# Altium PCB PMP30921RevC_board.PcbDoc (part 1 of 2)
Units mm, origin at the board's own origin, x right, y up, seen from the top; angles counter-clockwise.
Board outline 80.01 x 39.37 mm, 2 copper layers (Top Layer, Bottom Layer), stack 1.575 mm thick; 86 components, 35 nets, 198 pads, 30 vias.
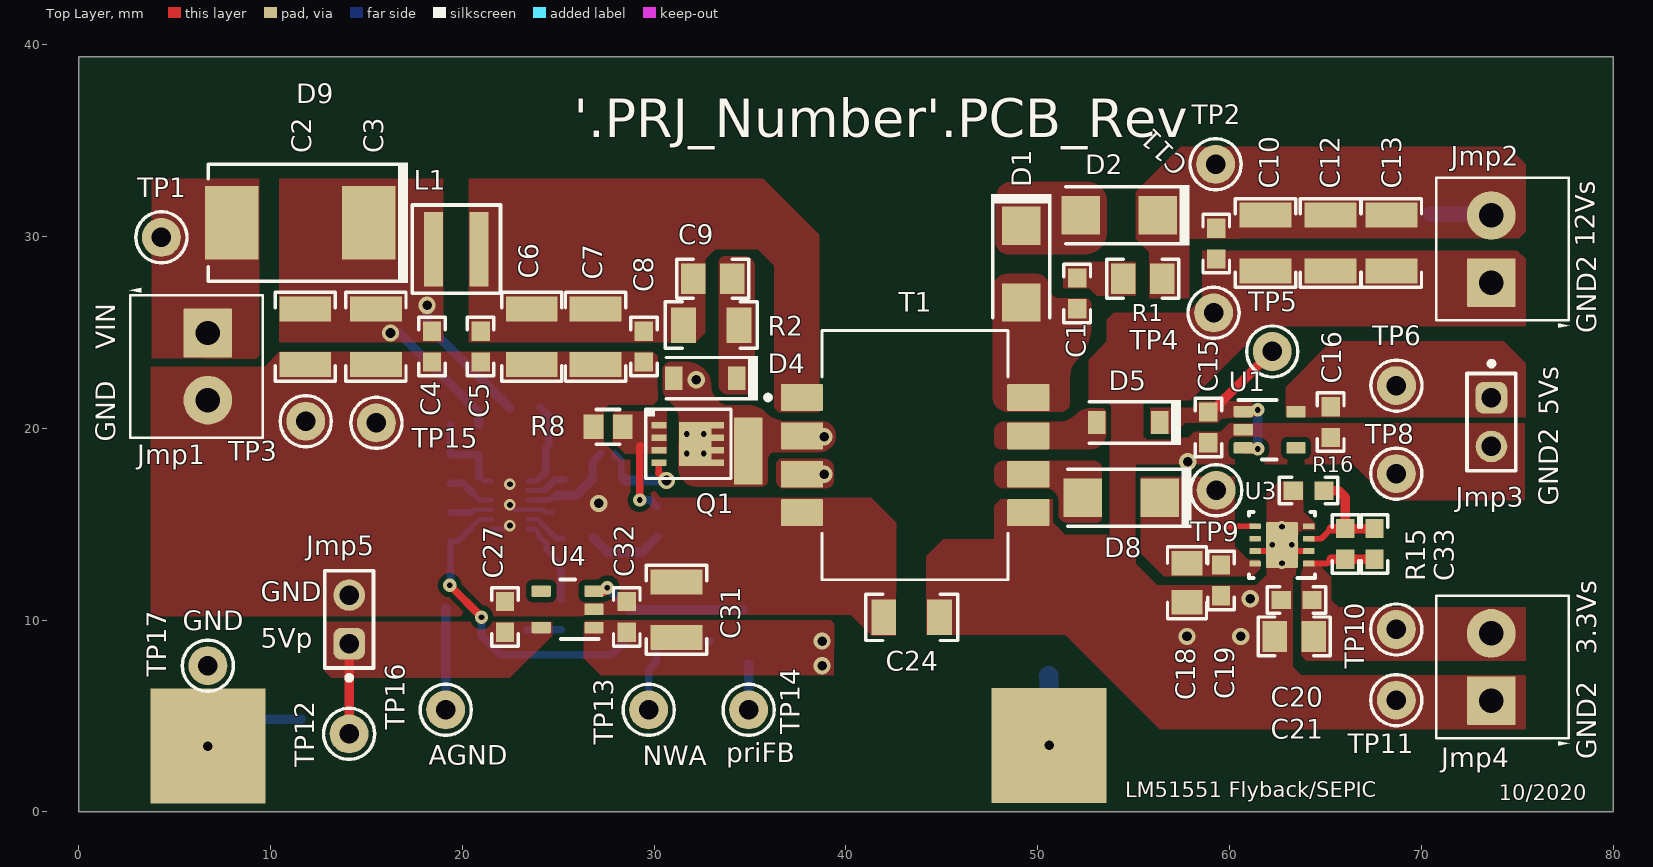
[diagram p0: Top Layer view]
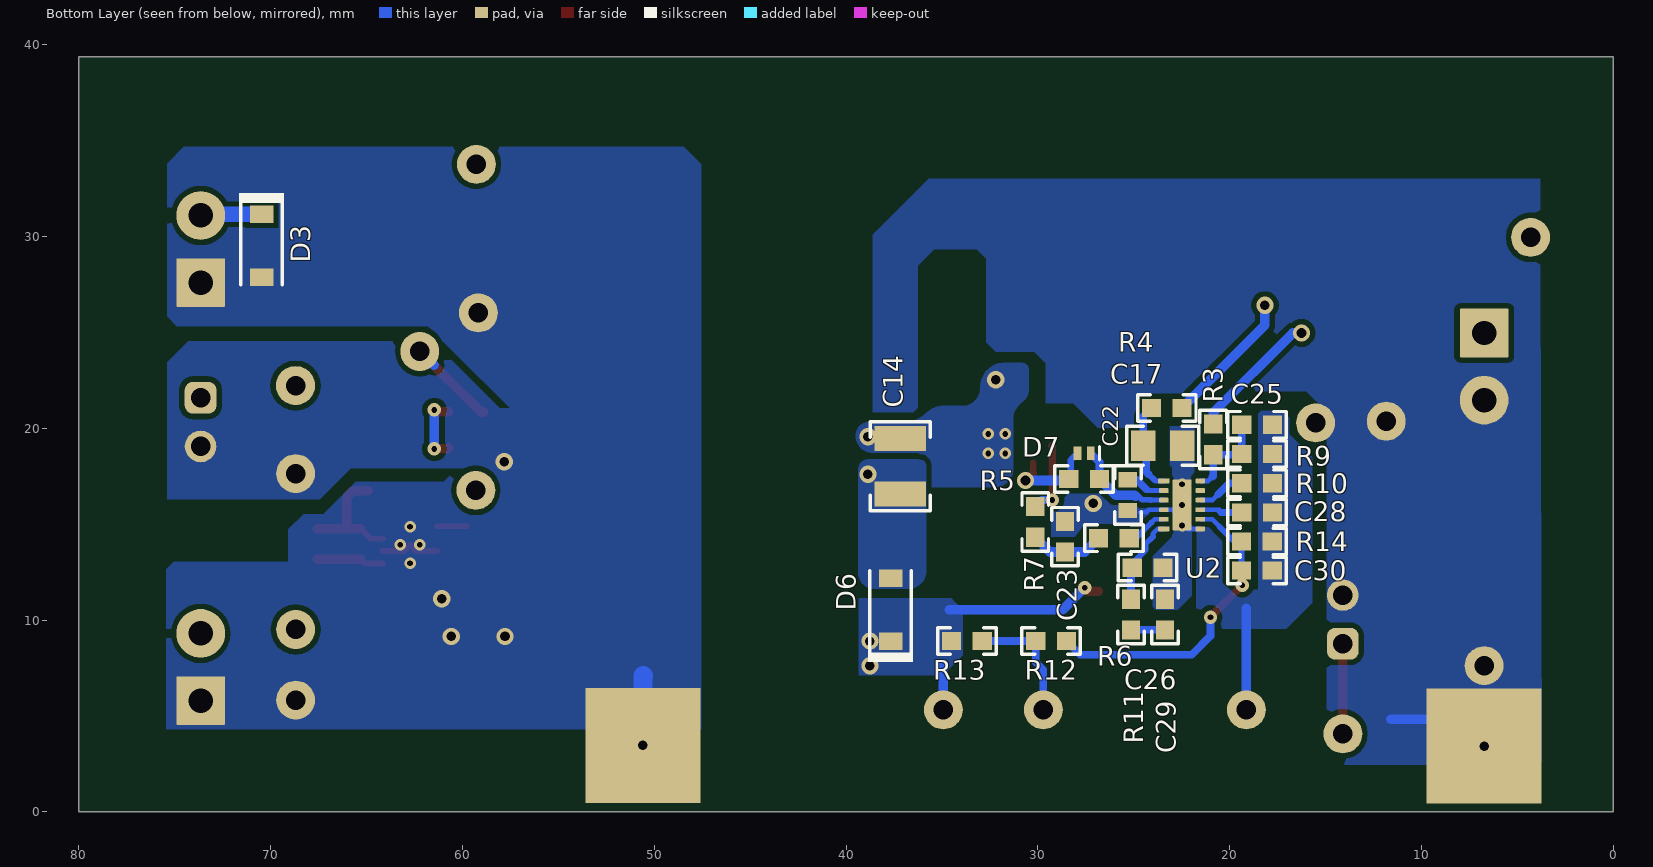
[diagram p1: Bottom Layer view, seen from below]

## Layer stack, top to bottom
Top Solder: solder mask 0.0102, Solder Resist, Dk 3.5
Top Layer: signal copper 0.0356
Dielectric1: core 1.5037, FR-4, Dk 4.8
Bottom Layer: signal copper 0.0356
Bottom Solder: solder mask 0.0102, Solder Resist, Dk 3.5

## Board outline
0,0 80.01,0 80.01,39.37 0,39.37

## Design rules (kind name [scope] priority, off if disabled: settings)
AcuteAngle [All] p1: minimum=4.50000000000000E+0001 checktracksonly=FALSE
AssemblyTestPointUsage [All] p1: valid=2
BoardOutlineClearance BoardOutlineClearance_MountingHoles [OnCopper and InComponentClass('Mounting Holes')] p1: gap=1 ignorepadtopadclearanceinfootprint=FALSE
BoardOutlineClearance BoardOutlineClearance_Poly [OnCopper and IsPoly] p2: gap=0.635 ignorepadtopadclearanceinfootprint=FALSE
BoardOutlineClearance [OnCopper and Not InComponentClass('Logo') and not InComponentClass('FiducialMark') and not InRegion(1000,500,4000,800) and not InPoly] p3: gap=1.905 ignorepadtopadclearanceinfootprint=FALSE
Clearance Clearance_Keepouts [((IsTrack Or IsArc) And Not InPoly) And IsFree and IsKeepOut vs ((IsTrack Or IsArc) And Not InPoly) And IsFree and IsKeepOut] p1: gap=0 ignorepadtopadclearanceinfootprint=FALSE
Clearance Clearance_Poly [InPolygon] p2: gap=0.28 ignorepadtopadclearanceinfootprint=TRUE
Clearance Clearance_FiducialMark [IsKeepOut and InComponentClass('FiducialMark') vs IsPad and InComponentClass('FiducialMark')] p3: gap=0 ignorepadtopadclearanceinfootprint=FALSE
Clearance [All] p4: gap=0.2 ignorepadtopadclearanceinfootprint=TRUE
ComponentClearance ComponentClearance_1 [All vs InComponent('TP7')] p1: gap=0.5 collisioncheckmode=3 verticalgap=0.254 showdistances=FALSE
ComponentClearance ComponentClearance_MountingHoles_FiducialMarks [InComponentClass('Mounting Holes') vs InComponentClass('FiducialMark')] p2: gap=1.27 collisioncheckmode=3 verticalgap=0.254 showdistances=FALSE
ComponentClearance ComponentClearance_Shunt [InComponentClass('Header') vs InComponentClass('Shunt')] p3: gap=0 collisioncheckmode=3 verticalgap=0 showdistances=FALSE
ComponentClearance ComponentClearance_Logo [InComponentClass('Logo')] p4: gap=1.27 collisioncheckmode=3 verticalgap=0.254 showdistances=FALSE
ComponentClearance ComponentClearance_ScrewToNut [(HasFootprint('NY PMS 440 0025 PH')) vs (HasFootprint('Keystone_1902C'))] p5: gap=0.127 collisioncheckmode=3 verticalgap=0.254 showdistances=FALSE
ComponentClearance ComponentClearance_MountingHoles [InComponentClass('Mounting Holes')] p6: gap=6.35 collisioncheckmode=3 verticalgap=2540 showdistances=FALSE
ComponentClearance ComponentClearance_SmallPassives [HasFootprint('0201*') or HasFootprint('0402*') or HasFootprint('0508') or HasFootprint('0603*') or HasFootprint('0612') or HasFootprint('0805*') or HasFootprint('0815*') or HasFootprint('0830*') or HasFootprint('1206*') or HasFootprint('1210*') or HasFootprint('1808*') or HasFootprint('1812*') or HasFootprint('1825*') or HasFootprint('2010*') or HasFootprint('2220*') or HasFootprint('2225*') or HasFootprint('2512*') or HasFootprint('2728*') or HasFootprint('3518*') or HasFootprint('X1-DFN1006-2') vs HasFootprint('0201*') or HasFootprint('0402*') or HasFootprint('0508') or HasFootprint('0603*') or HasFootprint('0612') or HasFootprint('0805*') or HasFootprint('0815*') or HasFootprint('0830*') or HasFootprint('1206*') or HasFootprint('1210*') or HasFootprint('1808*') or HasFootprint('1812*') or HasFootprint('1825*') or HasFootprint('2010*') or HasFootprint('2220*') or HasFootprint('2225*') or HasFootprint('2512*') or HasFootprint('2728*') or HasFootprint('3518*') or HasFootprint('X1-DFN1006-2')] p7: gap=0.38 collisioncheckmode=3 verticalgap=0.254 showdistances=FALSE
ComponentClearance ComponentClearance_THtoSMT [IsThruComponent vs IsSMTComponent] p8: gap=1.016 collisioncheckmode=3 verticalgap=0.762 showdistances=FALSE
ComponentClearance ComponentClearance_THtoTH [IsThruComponent vs IsThruComponent] p9: gap=0.762 collisioncheckmode=3 verticalgap=0.762 showdistances=FALSE
ComponentClearance [All] p10: gap=0.762 collisioncheckmode=3 verticalgap=0.254 showdistances=FALSE
DiffPairsRouting [All] p1: maxlimit=2.54 minlimit=0.254 mostfreqgap=0.254 toplayer_minwidth=0.381 toplayer_maxwidth=0.381 toplayer_prefwidth=0.381 bottomlayer_minwidth=0.381 bottomlayer_maxwidth=0.381 bottomlayer_prefwidth=0.381 maxuncoupledlength=25.4
FabricationTestPointUsage TestPointUsage [All] p1: valid=2 allowmultiple=FALSE
FabricationTestpoint Testpoint [All] p1: side=3 testpointundercomponent=TRUE minsize=1.016 maxsize=2.54 preferedsize=1.524 minholesize=0 maxholesize=1.016 preferedholesize=0.813 testpointgrid=0.025 allowsidetop=TRUE allowsidebottom=TRUE usegrid=TRUE gridtolerance=0
FanoutControl Fanout_LCC [IsLCC] p1: bgadir=Out bgaviamode=Centered fanoutstyle=Auto fanoutdirection=Alternating viagrid=0.025 // Fanout_LCC (Default Rule)
FanoutControl Fanout_BGA [IsBGA] p2: bgadir=Out bgaviamode=Centered fanoutstyle=Auto fanoutdirection=Alternating viagrid=0.025 // Fanout_BGA (Default Rule)
FanoutControl Fanout_Default [All] p4: bgadir=Out bgaviamode=Centered fanoutstyle=Auto fanoutdirection=Alternating viagrid=0.025 // Fanout_Default (Default Rule)
FanoutControl Fanout_Small [(CompPinCount < 5)] p5: bgadir=Out bgaviamode=Centered fanoutstyle=Auto fanoutdirection=OutThenIn viagrid=0.025 // Fanout_Small (Default Rule)
HoleSize [All] p1: absolutevalues=TRUE maxlimit=6.375 minlimit=0.3 maxpercent=80.000 minpercent=20.000
MinimumAnnularRing MinimumAnnularRing_ThermalPadVias [IsVia and InAnyComponent] p1: minimumring=0.15
MinimumAnnularRing [All] p2: minimumring=0.2
MinimumSolderMaskSliver MinimumSolderMaskSliver_Logo [InComponentClass('Logo') vs InComponentClass('Logo')] p1: minsoldermaskwidth=0.018
MinimumSolderMaskSliver [All] p2: minsoldermaskwidth=0.1
PlaneConnect [All] p1: planeconnectstyle=Relief reliefexpansion=0.254 reliefentries=4 reliefconductorwidth=0.254 reliefairgap=0.254
PolygonConnect [All] p1: connectstyle=Direct reliefconductorwidth=0.254 reliefentries=4 polygonreliefangle="90 Angle" airgapwidth=0.254
RoutingVias ThermalPadVias [IsVia and InAnyComponent] p1: holewidth=0.2 width=0.5 viastyle="Through Hole" minholewidth=0.2 minwidth=0.5 maxholewidth=0.33 maxwidth=0.6
RoutingVias [All] p2: holewidth=0.5 width=0.9 viastyle="Through Hole" minholewidth=0.3 minwidth=0.6 maxholewidth=1.016 maxwidth=1.651
SilkToBoardRegionClearance [Not ((IsComment or IsDesignator) And (Hide <> 'False')) and not InRegion(1000,500,4000,800)] p1:
SilkToSilkClearance SilkToSilkClearance_Pb-FreeLogo [(HasFootprint('Pb-Free_Overlay_Medium') OR HasFootprint('Pb-Free_Overlay_Small')) vs (HasFootprint('Pb-Free_Overlay_Medium') OR HasFootprint('Pb-Free_Overlay_Small'))] p1: silktosilkclearance=0
SilkToSilkClearance [All] p2: silktosilkclearance=0.1
SilkToSolderMaskClearance SilkToComponentPadClearance [(IsPad or IsFill or IsRegion) and InAnycomponent] p1: minsilkscreentomaskgap=0.127 clearancetoexposedcopper=TRUE
SilkToSolderMaskClearance "Silk to Solder Mask Opening" [All] p2: minsilkscreentomaskgap=0.1 clearancetoexposedcopper=FALSE
SolderMaskExpansion [All] p1: expansion=0.05 istentingtop=FALSE
UnRoutedNet [All] p1: checkbadconnections=TRUE
Width [All] p1: maxlimit=2.54 minlimit=0.152 preferedwidth=0.254 checkconnectedcopper=TRUE
14 further rules are at their usual default settings.

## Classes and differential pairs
component class Header: Jmp3 Jmp5
net class C33_Nets: FB NetC20_1
net class U4_Nets: GND NetC27_1 NetC31_1 NetU4_4
net class U3_Nets: FB GNDsec NetC18_1 NetC20_1 NetU3_6
net class U2_Nets: GND NetC17_1 NetC22_1 NetC25_1 NetC26_1 NetC28_1 NetC30_1 NetD7_1 NetR6_1 NetR10_2 NetU2_11
net class U1_Nets: GNDsec NetC15_1 NetC16_1 NetU1_4
net class TP17_Nets: GND
net class TP16_Nets: GND
net class TP15_Nets: GND
net class TP14_Nets: NetC31_1
net class TP13_Nets: NetR12_1
net class TP12_Nets: NetC27_1
net class TP11_Nets: GNDsec
net class TP10_Nets: NetC20_1
net class TP9_Nets: NetC18_1
net class TP8_Nets: GNDsec
net class TP6_Nets: NetC16_1
net class TP5_Nets: NetC15_1
net class TP4_Nets: GNDsec
net class TP3_Nets: GND
net class TP2_Nets: NetC10_1
net class TP1_Nets: NetD9_2
net class T1_Nets: GND GNDsec NetC1_2 NetC5_1 NetC14_1 NetC14_2 NetD5_2 NetD8_2
net class R16_Nets: FB GNDsec
net class R15_Nets: FB NetC20_1
net class R14_Nets: GND NetC30_1
net class R13_Nets: NetC31_1 NetR12_1
net class R12_Nets: NetC30_1 NetR12_1
net class R11_Nets: NetC26_1 NetC29_1
net class R10_Nets: GND NetR10_2
net class R9_Nets: GND NetC25_1
net class R8_Nets: GND NetQ1_1
net class R7_Nets: NetC23_1 NetQ1_1
net class R6_Nets: NetC23_1 NetR6_1
net class R5_Nets: NetD7_1 NetD7_2
net class R4_Nets: NetC2_1 NetC17_1
net class R3_Nets: NetC2_1 NetC25_1
net class R2_Nets: NetC5_1 NetC9_2
net class R1_Nets: NetC1_1 NetC10_1
net class Q1_Nets: NetC14_1 NetD7_2 NetQ1_1
net class L1_Nets: NetC2_1 NetC5_1
net class Jmp5_Nets: GND NetC27_1
net class Jmp4_Nets: GNDsec NetC20_1
net class Jmp3_Nets: GNDsec NetC16_1
net class Jmp2_Nets: GNDsec NetC10_1
net class Jmp1_Nets: GND NetD9_2
net class D9_Nets: NetC2_1 NetD9_2
net class D8_Nets: NetC18_1 NetD8_2
net class D7_Nets: NetD7_1 NetD7_2
net class D6_Nets: NetC14_2 NetC31_1
net class D5_Nets: NetC15_1 NetD5_2
net class D4_Nets: NetC9_2 NetC14_1
net class D3_Nets: GNDsec NetC10_1
net class D2_Nets: NetC10_1 NetD1_1
net class D1_Nets: NetC1_2 NetD1_1
net class C32_Nets: GND NetC31_1
net class C31_Nets: GND NetC31_1
net class C30_Nets: GND NetC30_1
net class C29_Nets: GND NetC29_1
net class C28_Nets: GND NetC28_1
net class C27_Nets: GND NetC27_1
net class C26_Nets: GND NetC26_1
net class C25_Nets: GND NetC25_1
net class C24_Nets: GND GNDsec
net class C23_Nets: GND NetC23_1
net class C22_Nets: GND NetC22_1
net class C21_Nets: GNDsec NetC20_1
net class C20_Nets: GNDsec NetC20_1
net class C19_Nets: GNDsec NetC18_1
net class C18_Nets: GNDsec NetC18_1
net class C17_Nets: GND NetC17_1
net class C16_Nets: GNDsec NetC16_1
net class C15_Nets: GNDsec NetC15_1
net class C14_Nets: NetC14_1 NetC14_2
net class C13_Nets: GNDsec NetC10_1
net class C12_Nets: GNDsec NetC10_1
net class C11_Nets: GNDsec NetC10_1
net class C10_Nets: GNDsec NetC10_1
net class C9_Nets: NetC5_1 NetC9_2
net class C8_Nets: GND NetC5_1
net class C7_Nets: GND NetC5_1
net class C6_Nets: GND NetC5_1
net class C5_Nets: GND NetC5_1
net class C4_Nets: GND NetC2_1
net class C3_Nets: GND NetC2_1
net class C2_Nets: GND NetC2_1
net class C1_Nets: NetC1_1 NetC1_2

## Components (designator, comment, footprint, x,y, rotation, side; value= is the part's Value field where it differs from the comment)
C1 "GRM1885C2A101JA01D" 0603#1 52.06,27.033 r270 top value=100pF
C2 "GRM32ER71H106KA12L" 1210_270 11.811,24.765 r270 top value=10uF
C3 "GRM32ER71H106KA12L" 1210_270 15.494,24.765 r270 top value=10uF
C4 "GCM188R71H104KA57D" 0603#1 18.415,24.257 r270 top value=0.1uF
C5 "GCM188R71H104KA57D" 0603#1 20.955,24.257 r270 top value=0.1uF
C6 "GRM32ER71H106KA12L" 1210_270 23.622,24.765 r270 top value=10uF
C7 "GRM32ER71H106KA12L" 1210_270 26.949,24.768 r270 top value=10uF
C8 "GCM188R71H104KA57D" 0603#1 29.464,24.257 r270 top value=0.1uF
C9 "GRM21BR72A103MA01L" 0805_HV 33.051,27.795 r0 top value=0.01uF
C10 "GRM32ER71E226KE15L" 1210_270 61.877,29.658 r270 top value=22uF
C11 "GCM188R71H104KA57D" 0603#1 59.309,29.629 r270 top value=0.1uF
C12 "GRM32ER71E226KE15L" 1210_270 65.268,29.658 r270 top value=22uF
C13 "GRM32ER71E226KE15L" 1210_270 68.443,29.658 r270 top value=22uF
C14 "GRM32ER71H106KA12L" 1210_270 37.178,18.016 r270 bottom value=10uF
C15 "GRM188Z71A106MA73D" 0603#1 58.896,20.046 r270 top value=10uF
C16 "GRM188Z71A106MA73D" 0603#1 65.278,20.32 r270 top value=10uF
C17 "GRM21BR71H105KA12L" 0805_HV 23.495,19.094 r180 bottom value=1uF
C18 "GRM21BZ71A226ME15L" 0805_HV 57.785,11.938 r270 top value=22uF
C19 "GRM188R71C104KA01D" 0603#1 59.563,12.065 r270 top value=0.1uF
C20 "GRM188R71C104KA01D" 0603#1 63.5,11.049 r180 top value=0.1uF
C21 "GRM21BZ71A226ME15L" 0805_HV 63.373,9.144 r180 top value=22uF
C22 "GRM188R71C105KA12D" 0603#2 25.312,16.514 r270 bottom value=1uF
C23 "GRM188R71E102KA01D" 0603#1 28.584,14.346 r90 bottom value=1000pF
C24 "GRM31BR73A102KW01L" 1206 43.424,10.142 r180 top value=1000pF
C25 "GRM1885C1H100JA01D" 0603#1 18.571,20.179 r180 bottom value=10pF
C26 "GRM188R71H331KA01D" 0603#1 24.279,12.731 r180 bottom value=330pF
C27 "GRM188Z71A106MA73D" 0603#1 22.225,10.16 r90 top value=10uF
C28 "GRM188R71C104KA01D" 0603#1 18.571,15.607 r180 bottom value=0.1uF
C29 "GRM188R71E104KA01D" 0603#1 23.368,10.287 r90 bottom value=0.1uF
C30 "GRM188R71H331KA01D" 0603#1 18.581,12.577 r180 bottom value=330pF
C31 "GRM32ER71A476KE15L" 1210_270 31.168,10.542 r90 top value=47uF
C32 "GRM188Z71A106MA73D" 0603#1 28.575,10.16 r90 top value=10uF
C33 "GRM188R71E103KA01D" 0603#1 67.564,13.97 r90 top value=0.01uF (schematic designator C?)
D1 "B1100-13-F" SMA 49.139,28.557 r270 top value=100V
D2 "B1100-13-F" SMA 54.251,31.097 r180 top value=100V
D3 "MMSZ5245B-7-F" SOD-123 70.475,29.522 r270 bottom value=15V
D4 "MBR0580-TP" SOD-123 32.67,22.609 r180 top value=80V
D5 "MBR0580-TP" SOD-123 54.727,20.302 r180 top value=80V
D6 "MBR0580-TP" SOD-123 37.678,10.542 r90 bottom value=80V
D7 "BAT54LP-7" X1-DFN1006-2 27.588,18.689 r0 bottom value=30V
D8 "B160-13-F" SMA 54.356,16.383 r180 top value=60V
D9 "B360-13-F" SMC 11.547,30.716 r180 top value=60V
Jmp1 "ED555/2DS" TERM_BLK_ED555-2DS 6.731,24.968 r270 top
Jmp2 "ED555/2DS" TERM_BLK_ED555-2DS 73.65,27.592 r90 top
Jmp3 "TSW-102-07-G-S" TSW-102-07-G-S 73.66,20.32 r270 top
Jmp4 "ED555/2DS" TERM_BLK_ED555-2DS 73.65,5.799 r90 top
Jmp5 "TSW-102-07-G-S" TSW-102-07-G-S 14.097,10.033 r90 top
L1 "XEL4030-222MEB" XEL4030_310 19.685,29.337 r0 top value=2.2uH
Q1 "BSZ440N10NS3 G" PG-TSDSON-8 31.789,19.181 r0 top value=100V
R1 "CRCW0805100RJNEA" 0805_HV 55.481,27.795 r0 top value=100
R2 "CRCW120649K9FKEA" 1206 32.982,25.382 r180 top value=49.9k
R3 "CRCW0603340KFKEA" 0603#1 20.857,19.417 r90 bottom value=340k
R4 "CRCW060310R0FKEAHP" 0603#1 23.279,21.062 r180 bottom value=10.0
R5 "CRCW060310R0FKEA" 0603#1 27.588,17.352 r0 bottom value=10.0
R6 "CRCW06030000Z0EA" 0603#1 26.035,14.268 r0 bottom value=0
R7 "CRCW0603100RFKEA" 0603#1 30.138,15.117 r90 bottom value=100
R8 "WSLP0805R0300FEB" WSLP0805 27.598,20.07 r0 top value=0.03
R9 "CRCW060368K1FKEA" 0603#1 18.571,18.655 r0 bottom value=68.1k
R10 "CRCW060386K6FKEA" 0603#1 18.571,17.131 r0 bottom value=86.6k
R11 "CRCW060320K0FKEA" 0603#1 25.146,10.287 r90 bottom value=20.0k
R12 "CRCW06035K11FKEA" 0603#1 29.309,8.908 r180 bottom value=5.11k
R13 "CRCW060349R9FKEA" 0603#1 33.701,8.905 r0 bottom value=49.9
R14 "CRCW06031K00FKEA" 0603#1 18.581,14.101 r0 bottom value=1.00k
R15 "CRCW060327K4FKEA" 0603#1 66.04,13.97 r270 top value=27.4k
R16 "CRCW06035K49FKEA" 0603#1 64.125,16.746 r0 top value=5.49k
T1 "A6154" FP-A6154_PTH_XFRMR_9MM7_13MM0-MFG 43.609,18.603 r0 top
TP1 "5000" Keystone5000 4.308,29.954 r90 top value=Red
TP2 "5000" Keystone5000 59.277,33.764 r90 top value=Red
TP3 "5001" Keystone5001 11.836,20.366 r90 top value=Black
TP4 "5001" Keystone5001 59.172,26.017 r90 top value=Black
TP5 "5000" Keystone5000 62.23,24.003 r90 top value=Red
TP6 "5000" Keystone5000 68.707,22.225 r90 top value=Red
TP8 "5001" Keystone5001 68.697,17.635 r90 top value=Black
TP9 "5000" Keystone5000 59.309,16.764 r90 top value=Red
TP10 "5000" Keystone5000 68.697,9.507 r90 top value=Red
TP11 "5001" Keystone5001 68.697,5.824 r90 top value=Black
TP12 "5000" Keystone5000 14.097,4.064 r90 top value=Red
TP13 "5003" Keystone5003 29.718,5.32 r90 top
TP14 "5000" Keystone5000 34.931,5.316 r90 top value=Red
TP15 "5001" Keystone5001 15.519,20.278 r90 top value=Black
TP16 "5001" Keystone5001 19.133,5.32 r90 top value=Black
TP17 "5001" Keystone5001 6.731,7.62 r90 top value=Black
U1 "TPS76350QDBVRQ1" DBV0005A_N 62.093,19.921 r0 top
U2 "LM51551QDSSTQ1" DSS0012C 22.479,16.002 r180 bottom
U3 "TPS74501PQWDRBRQ1" DRB0008J 62.735,13.914 r180 top
U4 "TPS76350QDBVRQ1" DBV0005A_N 25.488,10.559 r180 top

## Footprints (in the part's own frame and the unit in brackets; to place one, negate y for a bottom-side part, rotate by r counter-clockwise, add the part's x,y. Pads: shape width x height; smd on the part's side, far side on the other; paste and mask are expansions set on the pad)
0603#1 [mm] "0603 from SM-752 data"
  rect 1x0.95 smd: 1(-0.8,0) 2(0.8,0)
  silkscreen extent -1.52,-0.69 1.52,0.69, body extent -0.87,-0.47 0.87,0.47, height 1
0603#2 [mm] "0603 from SM-752 data"
  rect 0.8x0.95 smd: 1(-0.8,0) 2(0.8,0)
  silkscreen extent -1.52,-0.69 1.52,0.69, body extent -0.87,-0.47 0.87,0.47, height 1
0805_HV [mil] "0805 with 30mil clearance between pads"
  rect 50x63 smd: 1(-40,0) 2(40,0)
  silkscreen extent -74,-40 74,40, body extent -43,-29 43,29, height 57
1206 [mm] "1206 from SM-752 data"
  rect 1.3x1.85 smd: 1(-1.45,0) 2(1.45,0)
  silkscreen extent -2.4,-1.21 2.4,1.21, body extent -1.7,-0.9 1.7,0.9, height 1.35
1210_270 [mm] "1210"
  rect 1.3x2.7 smd: 1(-1.45,0) 2(1.45,0)
  silkscreen extent -2.32,-1.57 2.32,1.57, body extent -1.7,-1.35 1.7,1.35, height 2.7
DBV0005A_N [mm] "SOT23, 5-Leads, Body 2.9x1.6mm, Pitch 0.95mm, Lead Span 2.8mm, IPC Medium Density"
  rrect17% 1x0.6 smd: 1(-1.375,0.95) 2(-1.375,0) 3(-1.375,-0.95) 4(1.375,-0.95) 5(1.375,0.95)
  silkscreen extent -1.63,-1.55 0.38,1.55, body extent -1.42,-1.46 1.42,1.46, height 1.09
DRB0008J [mm] "VSON-8"
  rrect33% 0.6x0.31 smd: 1(-1.4,0.975) 2(-1.4,0.325) 3(-1.4,-0.325) 4(-1.4,-0.975) 5(1.4,-0.975) 6(1.4,-0.325) 7(1.4,0.325) 8(1.4,0.975)
  rrect6% 1.65x2.4 smd paste-1.2: 9(0,0)
  silkscreen extent -1.73,-1.73 1.73,1.73, body extent -1.55,-1.55 1.55,1.55, height 1.01
DSS0012C [mm] "WSON-12"
  rrect40% 0.6x0.25 smd: 1(-0.95,1.25) 6(-0.95,-1.25)
  rrect40% 0.5x0.25 smd: 2(-0.95,0.75) 3(-0.95,0.25) 4(-0.95,-0.25) 5(-0.95,-0.75) 7(0.95,-1.25) 8(0.95,-0.75) 9(0.95,-0.25) 10(0.95,0.25) 11(0.95,0.75) 12(0.95,1.25)
  rrect11% 0.95x1.17 on Bottom Paste: 13(0,-0.685) 13(0,0.685)
  rrect11% 1x2.65 smd paste-0.5: 13(0,0)
  body extent -1,-1.5 1,1.5, height 0.81
FP-A6154_PTH_XFRMR_9MM7_13MM0-MFG [mm]
  rrect7% 2.2x1.4 smd paste+0 mask+0: 1(-5.9,3) 2(-5.9,1) 3(-5.9,-1) 4(-5.9,-3) 5(5.9,-3) 6(5.9,-1) 7(5.9,1) 8(5.9,3)
  silkscreen extent -7.8,-6.5 4.85,6.5, body extent -6.9,-6.6 6.9,6.6, height 0.25
Keystone5000 [mil] "For Keystone 500x miniature loop terminals"
  round 80 hole 40: 1(0,0)
  silkscreen extent -52,-52 52,52, body extent -49,-49 49,49, height 182
Keystone5001 [mil] "For Keystone 500x miniature loop terminals"
  round 80 hole 40: 1(0,0)
  silkscreen extent -52,-52 52,52, body extent -49,-49 49,49, height 182
Keystone5003 [mil] "For Keystone 500x miniature loop terminals"
  round 80 hole 40: 1(0,0)
  silkscreen extent -52,-52 52,52, body extent -49,-49 49,49, height 182
PG-TSDSON-8 [mm] "Infineon recommended land pattern"
  rect 0.8x0.34 smd: 1(-1.538,0.975) 2(-1.538,0.325) 3(-1.538,-0.325) 4(-1.538,-0.975)
  rect 0.65x0.34 smd: 5(1.538,-0.975) 6(1.538,-0.325) 7(1.538,0.325) 8(1.538,0.975)
  rect 1.71x2.29 smd: 9(0.358,0)
  silkscreen extent -2.22,-1.8 2.22,1.8, body extent -1.7,-1.7 1.7,1.7, height 1.1
SMA [mm] "Molded Diode, 2-Leads, Body 4.3x2.6mm, IPC Medium Density, based on OnSemi component dimensions and land pattern"
  rect 2x2 smd: 1(-2,0) 2(2,0)
  silkscreen extent -3.66,-1.57 2.79,1.57, body extent -2.6,-1.3 2.6,1.3, height 2.42
SMC [mil] "Molded Diode, 2-Leads, Body 6.9x5.8mm, IPC Medium Density, based on OnSemi component dimensions and land patterns"
  rect 110x150 smd: 1(-140.49,0) 2(140.49,0)
  silkscreen extent -221,-123 189,124, body extent -156,-116 156,116, height 91
SOD-123 [mm] "On Semi recommended land pattern"
  rect 0.915x1.22 smd: 1(-1.637,0) 2(1.637,0)
  silkscreen extent -2.74,-1.17 2.03,1.17, body extent -1.93,-0.9 1.93,0.9, height 1.35
TERM_BLK_ED555-2DS [mil]
  rrect4% 100x100 hole 50: 1(0,0)
  round 100 hole 50: 2(138,0)
  silkscreen extent -93,-161 215,113, body extent -69,-150 207,106, height 323
TSW-102-07-G-S [mm] "Samtec 100mil, 1x2, 230 mil above insulator"
  rrect50% 1.65x1.65 hole 1.016: 1(-1.27,0)
  round 1.65 hole 1.016: 2(1.27,0)
  silkscreen extent -3.17,-1.27 2.54,1.27, body extent -2.54,-1.27 2.54,1.27, height 8.38
WSLP0805 [mm] "Vishay"
  rect 1.02x1.27 smd: 1(-0.76,0) 2(0.76,0)
  silkscreen extent -0.6,-0.9 0.6,0.9, body extent -1.14,-0.76 1.14,0.76, height 0.64
X1-DFN1006-2 [mm] "DIODES, INC"
  rect 0.4x0.7 smd: 1(-0.35,0) 2(0.35,0)
  silkscreen extent -0.8,-0.35 -0.8,0.35, body extent -0.54,-0.34 0.54,0.34, height 0.53
XEL4030_310 [mm] "SMD, 2-Leads, Body 4x4mm, Pitch 2.37mm"
  rect 0.98x3.9 smd: 1(-1.185,0) 2(1.185,0)
  silkscreen extent -2.3,-2.3 2.3,2.3, body extent -2.15,-2.15 2.15,2.15, height 3.1

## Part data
C1: "CAP, CERM, 100 pF, 100 V,+/- 5%, C0G/NP0, 0603", Cap_Case=0603, Manufacturer=MuRata, Supplier Part Number 1=490-1351-1-ND, TempCo=C0G/NP0, Tolerance_%=5, Value2=100V, ValueDisplayed=100pF
C2 C3 C6 C7 C14: "CAP, CERM, 10 µF, 50 V,+/- 10%, X7R, 1210", Cap_Case=1210, Manufacturer=MuRata, Supplier Part Number 1=490-6544-1-ND, TempCo=X7R, Tolerance_%=10, Value2=50V, ValueDisplayed=10µF
C4 C5 C8 C11: "CAP, CERM, 0.1 µF, 50 V, +/- 10%, X7R, 0603", Cap_Case=0603, Manufacturer=MuRata, Supplier Part Number 1=490-4779-1-ND, TempCo=X7R, Tolerance_%=10, Value1="0.02 ohm", Value2=50V, ValueDisplayed=0.1µF
C9: library part GRM21BR72A473KA01L, "CAP, CERM, 0.047 µF, 100 V,+/- 10%, X7R, 0805", Cap_Case=0805, Manufacturer=MuRata, Supplier Part Number 1=490-1653-1-ND, TempCo=X7R, Tolerance_%=20, Value1=Unknown, Value2=100V, ValueDisplayed=0.01µF
C10 C12 C13: "CAP, CERM, 22 µF, 25 V,+/- 10%, X7R, 1210", Cap_Case=1210, Manufacturer=MuRata, Supplier Part Number 1=490-5313-1-ND, TempCo=X7R, Tolerance_%=10, Value1="0.002334 ohm", Value2=25V, ValueDisplayed=22µF
C15 C16 C27 C32: library part CMP-0007497-5, "CAP, CERM, 10 uF, 10 V, +/- 20%, X7R, 0603", Cap_Case=0603, Manufacturer=MuRata, Supplier Part Number 1=81-GRM188Z71A106MA3D, TempCo=X7R, Tolerance_%=20%, Value1=Unknown, Value2=10V, ValueDisplayed=10uF
C17: "CAP, CERM, 1 µF, 50 V,+/- 10%, X7R, 0805", Cap_Case=0805, Manufacturer=MuRata, Supplier Part Number 1=490-4736-1-ND, TempCo=X7R, Tolerance_%=10, Value2=50V, ValueDisplayed=1µF
C18 C21: "CAP, CERM, 22 µF, 10 V,+/- 20%, X7R, 0805", Cap_Case=0805, Manufacturer=MuRata, Supplier Part Number 1=81-GRM21BZ71A226ME5L, TempCo=X7R, Tolerance_%=20, Value2=10V, ValueDisplayed=22µF
C19 C20 C28: "CAP, CERM, 0.1 µF, 16 V,+/- 10%, X7R, 0603", Cap_Case=0603, Manufacturer=MuRata, Supplier Part Number 1=490-1532-1-ND, TempCo=X7R, Tolerance_%=10, Value2=16V, ValueDisplayed=0.1µF
C22: "CAP, CERM, 1 µF, 16 V, +/- 10%, X7R, 0603", Cap_Case=0603, Manufacturer=MuRata, Supplier Part Number 1=490-3900-1-ND, TempCo=X7R, Tolerance_%=10, Value1="0.011 ohm", Value2=16V, ValueDisplayed=1µF
C23: "CAP, CERM, 1000 pF, 25 V,+/- 10%, X7R, 0603", Cap_Case=0603, Manufacturer=MuRata, Supplier Part Number 1=GRM188R71E102KA01D-ND, TempCo=X7R, Tolerance_%=10, Value2=25V, ValueDisplayed=1000pF
C24: "CAP, CERM, 1000 pF, 1000 V,+/- 10%, X7R, 1206", Cap_Case=1206, Manufacturer=MuRata, Supplier Part Number 1=490-3494-1-ND, TempCo=X7R, Tolerance_%=10, Value2=1000V, ValueDisplayed=1000pF
C25: "CAP, CERM, 10 pF, 50 V,+/- 5%, C0G/NP0, 0603", Cap_Case=0603, Manufacturer=MuRata, Supplier Part Number 1=490-1403-1-ND, TempCo=C0G/NP0, Tolerance_%=5, Value2=50V, ValueDisplayed=10pF
C26: "CAP, CERM, 330 pF, 50 V,+/- 10%, X7R, 0603", Cap_Case=0603, Manufacturer=MuRata, Supplier Part Number 1=490-1486-1-ND, TempCo=X7R, Tolerance_%=10, Value2=50V, ValueDisplayed=330pF
C29: "CAP, CERM, 0.1 µF, 25 V,+/- 10%, X7R, 0603", Cap_Case=0603, Manufacturer=MuRata, Supplier Part Number 1=490-1524-1-ND, TempCo=X7R, Tolerance_%=10, Value2=25V, ValueDisplayed=0.1µF
C30: library part GRM188R71E102KA01D, "CAP, CERM, 1000 pF, 25 V,+/- 10%, X7R, 0603", Cap_Case=0603, Manufacturer=MuRata, Supplier Part Number 1=490-1486-1-ND, TempCo=X7R, Tolerance_%=10, Value2=50V, ValueDisplayed=330pF
C31: "CAP, CERM, 47 µF, 10 V,+/- 10%, X7R, 1210", Cap_Case=1210, Manufacturer=MuRata, Supplier Part Number 1=490-5312-1-ND, TempCo=X7R, Tolerance_%=10, Value2=10V, ValueDisplayed=47µF
C33: "CAP, CERM, 0.01 µF, 25 V,+/- 10%, X7R, 0603", Cap_Case=0603, Manufacturer=MuRata, Supplier Part Number 1=490-1520-1-ND, TempCo=X7R, Tolerance_%=10, Value2=25V, ValueDisplayed=0.01µF
D1 D2: "Diode, Schottky, 100 V, 1 A, SMA", Manufacturer="Diodes Inc.", Supplier Part Number 1=B1100-FDICT-ND, Value1=1A, Value2=0.79V
D3: "Diode, Zener, 15 V, 500 mW, SOD-123", Manufacturer="Diodes Inc.", Power_W=0.5, Supplier Part Number 1=MMSZ5245B-FDICT-ND, Value1=0.5W
D4: library part MBR1H100SFT3G, "Diode, Schottky, 100 V, 1 A, SOD-123FL", Manufacturer="Micro Commercial Components", Supplier Part Number 1=MBR0580-TPMSCT-ND, Value1=0.5A, Value2=0.8V
D5 D6: "Diode, Schottky, 80 V, 0.5 A, SOD-123", Manufacturer="Micro Commercial Components", Supplier Part Number 1=MBR0580-TPMSCT-ND, Value1=0.5A, Value2=0.8V
D7: "Diode, Schottky, 30 V, 0.2 A, 1.00x0.50x0.60mm", Manufacturer="Diodes Inc.", Supplier Part Number 1=BAT54LPDICT-ND, Value1=0.2A, Value2=1V
D8: "Diode, Schottky, 60 V, 1 A, SMA", Manufacturer="Diodes Inc.", Supplier Part Number 1=B160-FDICT-ND, Value1=1A, Value2=0.7V
D9: "Diode, Schottky, 60 V, 3 A, SMC", Manufacturer="Diodes Inc.", Supplier Part Number 1=B360-FDICT-ND, Value1=3A, Value2=0.7V
Jmp1 Jmp2 Jmp4: "Terminal Block, 6A, 3.5mm Pitch, 2-Pos, TH", Manufacturer="On-Shore Technology", Supplier Part Number 1=ED1514-ND
Jmp3 Jmp5: library part ED555/2DS, "Terminal Block, 6A, 3.5mm Pitch, 2-Pos, TH", Color=Black, Current_A=6.3A, Manufacturer=Samtec, Supplier Part Number 1=SAM1029-02-ND, Voltage_V=550V
L1: "Inductor, Shielded, Composite, 2.2 µH, 6.1 A, 0.0201 ohm, AEC-Q200 Grade 1, SMD", Manufacturer=Coilcraft, Value1="0.0201 ohm", Value2=6.1A, ValueDisplayed=2.2µH
Q1: "MOSFET, N-CH, 100 V, 18 A, PG-TSDSON-8", Alternate Manufacturer=None, Manufacturer="Infineon Technologies", Supplier Part Number 1="BSZ440N10NS3 GINCT-ND", Value1="? ohm", Value2="6.8 nC"
R1: "RES, 100, 5%, 0.125 W, 0805", Manufacturer=Vishay-Dale, Power_W=0.125, Supplier Part Number 1=541-100ACT-ND, TempCo="200 ppm/C", Tolerance_%=5, Value1=5%, Value2=0.125W, Value_Code=100R, ValueDisplayed=100
R2: library part CRCW120610K0FKEAHP, "RES, 10.0 k, 1%, 0.5 W, 1206", Manufacturer=Vishay-Dale, Power_W=0.25, Supplier Part Number 1=541-49.9KFCT-ND, TempCo="100 ppm/C", Tolerance_%=1, Value1=1%, Value2=0.25W, Value_Code=49k9, ValueDisplayed=49.9k
R3: "RES, 340 k, 1%, 0.1 W, 0603", Manufacturer=Vishay-Dale, Power_W=0.1, Supplier Part Number 1=541-340KHCT-ND, TempCo="100 ppm/C", Tolerance_%=1, Value1=1%, Value2=0.1W, Value_Code=340k
R4: "RES, 10.0, 1%, 0.25 W, 0603", Manufacturer=Vishay-Dale, Power_W=0.25, Supplier Part Number 1=541-10.0SCT-ND, TempCo="100 ppm/C", Tolerance_%=1, Value1=1%, Value2=0.25W, Value_Code=10R0, ValueDisplayed=10.0
R5: "RES, 10.0, 1%, 0.1 W, 0603", Manufacturer=Vishay-Dale, Power_W=0.1, Supplier Part Number 1=541-10.0HCT-ND, TempCo="100 ppm/C", Tolerance_%=1, Value1=1%, Value2=0.1W, Value_Code=10R0, ValueDisplayed=10.0
R6: "RES, 0, 5%, 0.1 W, 0603", Manufacturer=Vishay-Dale, Power_W=0.1, Supplier Part Number 1=541-0.0GCT-ND, TempCo="200 ppm/C", Tolerance_%=5, Value1=5%, Value2=0.1W, Value_Code=0000, ValueDisplayed=0
R7: "RES, 100, 1%, 0.1 W, 0603", Manufacturer=Vishay-Dale, Power_W=0.1, Supplier Part Number 1=541-100HCT-ND, TempCo="100 ppm/C", Tolerance_%=1, Value1=1%, Value2=0.1W, Value_Code=100R, ValueDisplayed=100
R8: "RES, 0.03, 1%, 0.5 W, 0805", Manufacturer=Vishay-Dale, Power_W=0.5, Supplier Part Number 1=WSLPB-.03CT-ND, TempCo="75 ppm/C", Tolerance_%=1, Value1=1%, Value2=0.5W, Value_Code=R030, ValueDisplayed=0.03
R9: library part CRCW060371K5FKEA, "RES, 71.5 k, 1%, 0.1 W, 0603", Manufacturer=Vishay-Dale, Power_W=0.1, Supplier Part Number 1=541-68.1KHCT-ND, TempCo="100 ppm/C", Tolerance_%=1, Value1=1%, Value2=0.1W, Value_Code=68k1, ValueDisplayed=68.1k
R10: "RES, 86.6 k, 1%, 0.1 W, 0603", Manufacturer=Vishay-Dale, Power_W=0.1, Supplier Part Number 1=541-86.6KHCT-ND, TempCo="100 ppm/C", Tolerance_%=1, Value1=1%, Value2=0.1W, Value_Code=86k6, ValueDisplayed=86.6k
R11: "RES, 20.0 k, 1%, 0.1 W, 0603", Manufacturer=Vishay-Dale, Power_W=0.1, Supplier Part Number 1=541-20.0KHCT-ND, TempCo="100 ppm/C", Tolerance_%=1, Value1=1%, Value2=0.1W, Value_Code=20k0, ValueDisplayed=20.0k
R12: library part CRCW08051K10FKEA, "RES, 1.10 k, 1%, 0.125 W, 0805", Manufacturer=Vishay-Dale, Power_W=0.1, Supplier Part Number 1=541-5.11KHCT-ND, TempCo="100 ppm/C", Tolerance_%=1, Value1=1%, Value2=0.1W, Value_Code=5k11, ValueDisplayed=5.11k
R13: "RES, 49.9, 1%, 0.1 W, 0603", Manufacturer=Vishay-Dale, Power_W=0.1, Supplier Part Number 1=541-49.9HCT-ND, TempCo="100 ppm/C", Tolerance_%=1, Value1=1%, Value2=0.1W, Value_Code=49R9, ValueDisplayed=49.9
R14: library part CRCW0603200RFKEA, "RES, 200, 1%, 0.1 W, 0603", Manufacturer=Vishay-Dale, Power_W=0.1, Supplier Part Number 1=541-1.00KHCT-ND, TempCo="100 ppm/C", Tolerance_%=1, Value1=1%, Value2=0.1W, Value_Code=1k00, ValueDisplayed=1.00k
R15: "RES, 27.4 k, 1%, 0.1 W, 0603", Manufacturer=Vishay-Dale, Power_W=0.1, Supplier Part Number 1=541-27.4KHCT-ND, TempCo="100 ppm/C", Tolerance_%=1, Value1=1%, Value2=0.1W, Value_Code=27k4, ValueDisplayed=27.4k
R16: "RES, 5.49 k, 1%, 0.1 W, 0603", Manufacturer=Vishay-Dale, Power_W=0.1, Supplier Part Number 1=541-5.49KHCT-ND, TempCo="100 ppm/C", Tolerance_%=1, Value1=1%, Value2=0.1W, Value_Code=5k49, ValueDisplayed=5.49k
T1: library part CMP-0090554-1, "TRANSFORMER", Manufacturer="MPS Industries", Operating Temperature Range="-40°C to +125°C", Voltage_Isolation_Vrms=500VDC
TP1 TP2 TP5 TP6 TP9 TP10 TP12 TP14: "Test Point, Miniature, Red, TH", Manufacturer=Keystone, Supplier Part Number 1=5000K-ND
TP3 TP4 TP8 TP11 TP15 TP16 TP17: "Test Point, Miniature, Black, TH", Manufacturer=Keystone, Supplier Part Number 1=5001K-ND
TP13: "Test Point, Miniature, Orange, TH", Color=Orange, Manufacturer=Keystone, Supplier Part Number 1=36-5003-ND
U1 U4: "Single Output Automotive LDO, 150 mA, Fixed 5 V Output, 2.7 to 10 V Input, 5-pin SOT-23 (DBV), -40 to 125 degC, Green (RoHS & no Sb/Br)", Alternate Manufacturer="Texas Instruments", Alternate PartNumber=Equivalent, Supplier Part Number 1=TPS76350QDBVRQ1-ND
U2: library part CMP-0081540-1, "Automotive Grade 2.2-MHz Wide Input Non-synchronous Boost Controller, DSS0012C (WSON-12)", Alternate Manufacturer="Texas Instruments", Alternate PartNumber=LM51551QDSSRQ1
U3: library part CMP-0860764-1, "500-mA LDO With Power-Good in Small Wettable Flank WSON Package, DRB0008J (VSON-8)", Alternate Manufacturer="Texas Instruments"

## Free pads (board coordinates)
  rect 6x6 hole 0.5: 13(6.731,3.429) 13(50.596,3.463)
  rect 1.5x3.5 smd: 14(34.905,18.817)

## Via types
v1: diameter 0.6, hole 0.3, Top Layer to Bottom Layer, 11 vias
v2: diameter 0.9, hole 0.5, Top Layer to Bottom Layer, 8 vias
v3: diameter 0.7, hole 0.3, Top Layer to Bottom Layer, tented top, 3 vias
v4: diameter 0.9, hole 0.5, Top Layer to Bottom Layer, tented top, 2 vias
v5: diameter 0.9, hole 0.5, Top Layer to Bottom Layer, tented both sides, 2 vias
v6: diameter 0.7, hole 0.3, Top Layer to Bottom Layer, tented bottom, 2 vias
v7: diameter 0.7, hole 0.3, Top Layer to Bottom Layer, 1 vias
v8: diameter 0.9, hole 0.5, Top Layer to Bottom Layer, tented bottom, 1 vias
